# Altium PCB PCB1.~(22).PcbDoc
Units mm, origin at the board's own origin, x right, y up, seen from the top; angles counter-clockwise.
Board outline 24 x 24.06 mm, 2 copper layers (Top Layer, Bottom Layer); 41 components, 34 nets, 175 pads, 49 vias.
Unrouted connection lines stored in the file: 1.
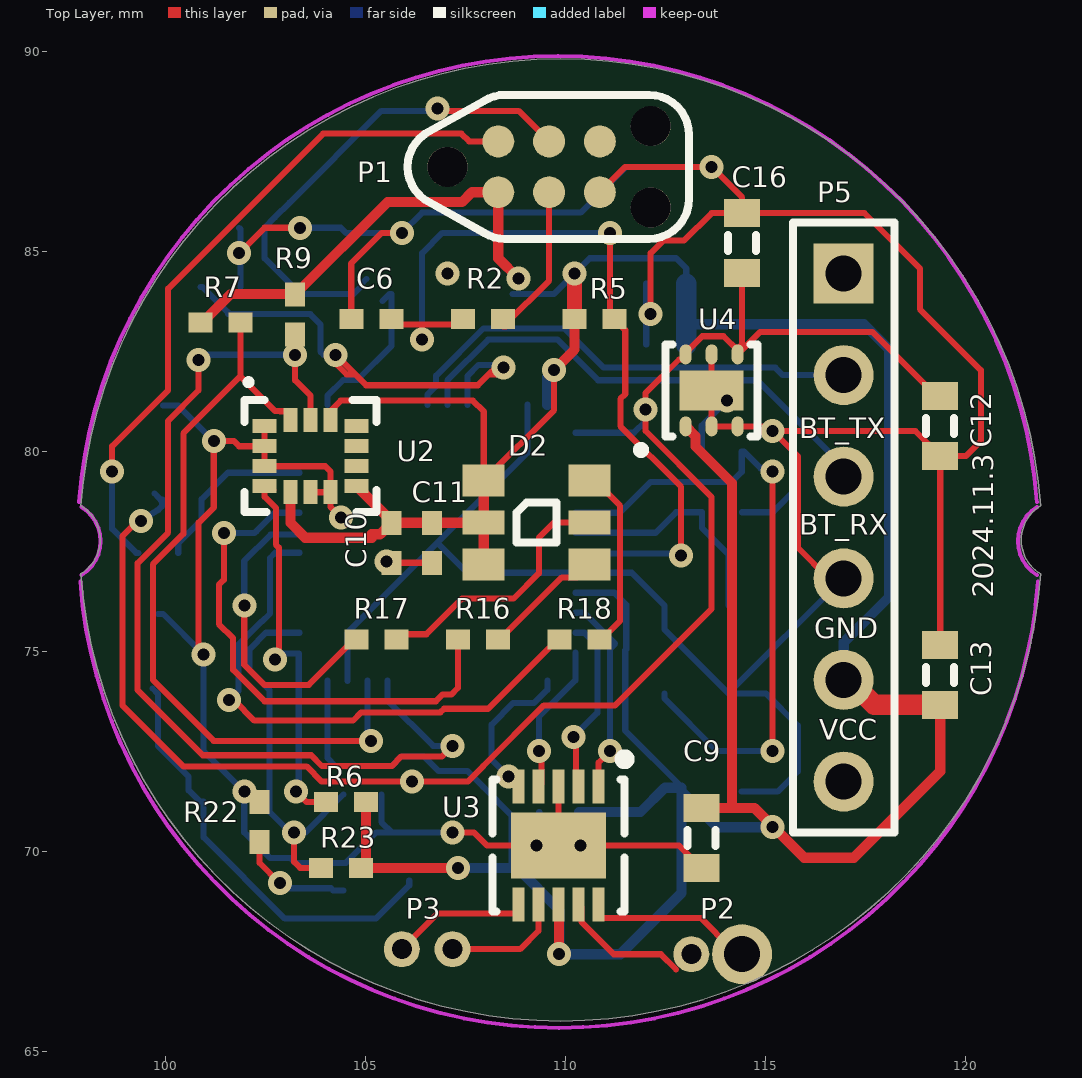
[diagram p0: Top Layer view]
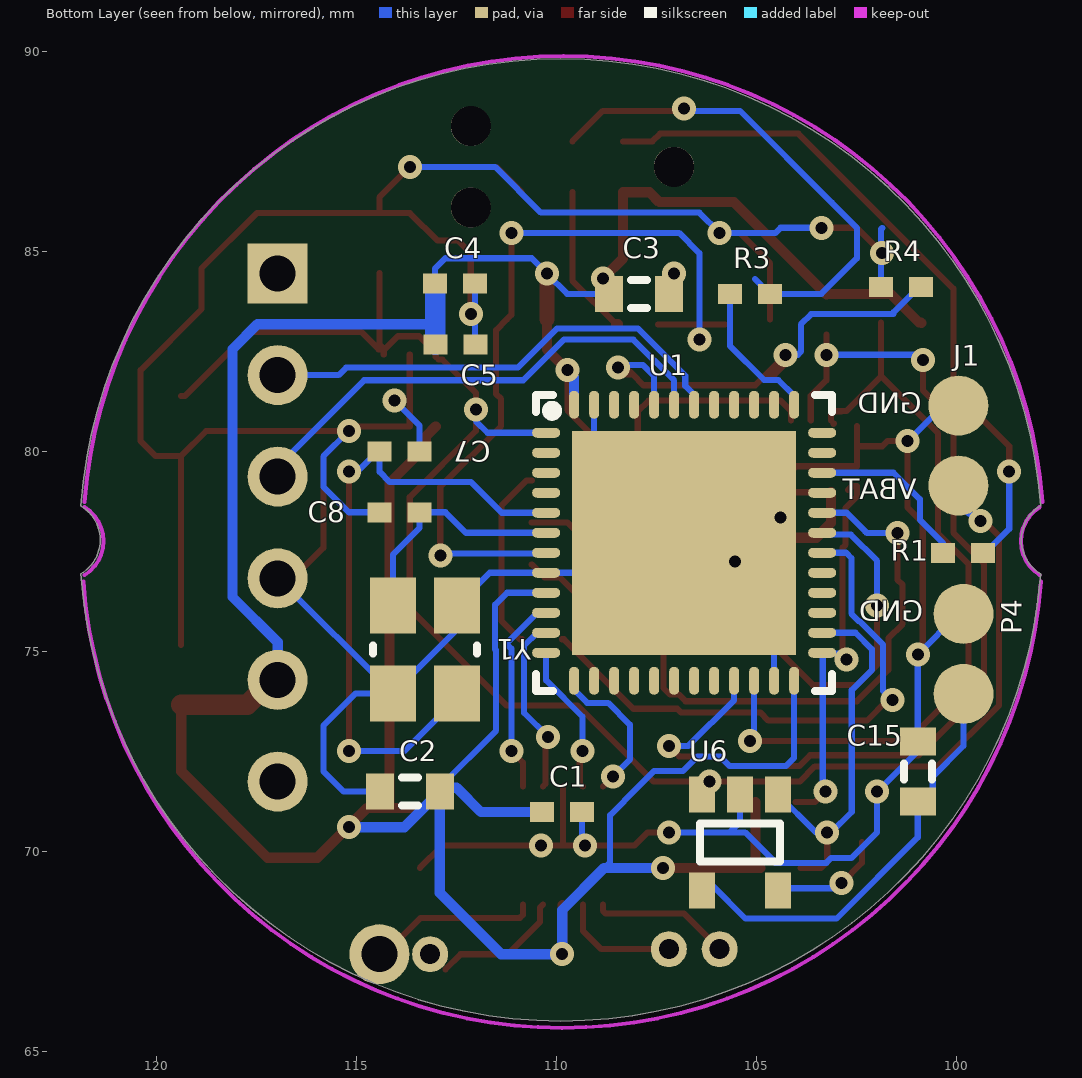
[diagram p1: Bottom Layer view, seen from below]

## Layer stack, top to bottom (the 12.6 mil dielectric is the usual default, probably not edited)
Top Solder: solder mask 0.0102, Solder Resist, Dk 3.5
Top Layer: signal copper 0.0356
Dielectric 1: dielectric 0.32, FR-4, Dk 4.8
Bottom Layer: signal copper 0.0356
Bottom Solder: solder mask 0.0102, Solder Resist, Dk 3.5

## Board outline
97.893,76.946 ccw(c97.392,77.796) 97.894,78.646 cw(c109.892,77.796) 121.89,78.648 121.891,78.646 ccw(c122.392,77.796) 121.89,76.946 cw(c109.892,77.796)

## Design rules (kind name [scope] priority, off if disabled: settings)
Clearance [All] p1: gap=0.254 except(0.127: Arc-Arc Track-SMDPad Arc-Track Arc-SMDPad Track-Track SMDPad-SMDPad)
PolygonConnect [All] p1: connectstyle=Relief reliefconductorwidth=0.254 reliefentries=4 polygonreliefangle="90 Angle" airgapwidth=0.254
RoutingVias [All] p1: holewidth=0.711 width=1.27 viastyle="Through Hole" minholewidth=0.711 minwidth=1.27 maxholewidth=0.711 maxwidth=1.27
SolderMaskExpansion [All] p1: expansion=0.102
UnpouredPolygon [All] p1: allowunpoured=FALSE
Width [All] p1: maxlimit=0.254 minlimit=0.127 preferedwidth=0.152 minimp=50.000000 maximp=50.000000 favimp=50.000000
29 further rules are at their usual default settings.

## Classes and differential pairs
net class MOTOR_CONTROL[1..4]: MOTOR_CONTROL1 MOTOR_CONTROL2 MOTOR_CONTROL3 MOTOR_CONTROL4
net class RGBLED[1..3]: RGBLED1 RGBLED2 RGBLED3

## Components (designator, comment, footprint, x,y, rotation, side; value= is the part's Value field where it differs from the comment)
C1 "10nF" 0402 109.855,70.993 r0 bottom
C2 "1uF" 0603 113.665,71.501 r180 bottom
C3 "4.7uF" 0603 107.938,83.947 r0 bottom
C4 "100nF" 0402 112.53,84.201 r0 bottom
C5 "100nF" 0402 112.522,82.677 r0 bottom
C6 "100nF" 0402 105.156,83.312 r0 top
C7 "22pF" 0402 113.919,80.01 r0 bottom
C8 "22pF" 0402 113.927,78.486 r180 bottom
C9 "10uF" 0603 113.411,70.346 r90 top
C10 "100nF" 0402 105.664,77.724 r90 top
C11 "100nF" 0402 106.68,77.724 r90 top
C12 "1uF" 0603 119.38,80.645 r90 top
C13 "1uF" 0603 119.38,74.422 r270 top
C15 "4.7uF" 0603 100.965,72.009 r270 bottom
C16 "4.7uF" 0603 114.427,85.217 r270 top
D2 "SMLVN6RGB1W1" "3.5x2.8 mm 6-SMD" 109.292,78.232 r0 top
J1 "78171-0002" "CHARGING PAD" 99.949,80.153 r90 bottom
P1 "TC2030-IDC-NL" TC2030-IDC-NL 109.601,87.122 r0 top
P2 "HEADER 2X1 0.05\" UNPOLARIZED" "HEADER 2X1 0.05\" - UNPOLARIZED"#1 113.792,67.437 r180 top
P3 "HEADER 2X1 0.05\" UNPOLARIZED" "HEADER 2X1 0.05\" - UNPOLARIZED"#2 106.553,67.564 r0 top
P4 "CHARGING PAD" "Charging Pad" 99.822,74.946 r90 bottom
P5 "Header 6" HDR1X6 116.967,84.455 r270 top
R1 "22R" 0402 99.83,77.47 r180 bottom
R2 "22R" 0402 107.95,83.312 r0 top
R3 "22R" 0402 105.164,83.947 r180 bottom
R4 "100K" 0402 101.384,84.121 r180 bottom
R5 "100K" 0402 110.736,83.312 r180 top
R6 "100K" 0402 104.521,71.247 r0 top
R7 "10K" 0402 101.384,83.232 r180 top
R9 "10K" 0402 103.251,83.431 r90 top
R16 "22.6R" 0402 107.823,75.311 r0 top
R17 "130R" 0402 105.283,75.311 r0 top
R18 "24.9R" 0402 110.363,75.311 r0 top
R22 "10K" 0402 102.362,70.739 r90 top
R23 "100K" 0402 104.394,69.596 r0 top
U1 "STM32F051C8U6" QFN50P700X700X60_HS-49L 106.807,77.724 r180 bottom
U2 "LSM6DS3" "LGA-14 2.5x3x0.86 mm 14L" 103.639,79.887 r0 top
U3 "A3901SEJTR-T" DFN50P300X300X75_HS-11N 109.839,70.153 r180 top
U4 "ADP122ACPZ-3.3-R7" "LFCSP-6 2.0X2.0X0.55" 113.665,81.534 r0 top
U6 "MCP73831T-2ACI/OT" SOT-23-OT5_L 105.41,70.231 r270 bottom
Y1 "7V-16.000MAAE-T" "3.2x2.5 CRYSTAL" 113.284,75.057 r90 bottom

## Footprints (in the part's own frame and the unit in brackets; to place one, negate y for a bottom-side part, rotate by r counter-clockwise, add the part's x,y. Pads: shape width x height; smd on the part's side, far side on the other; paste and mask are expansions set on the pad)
"3.2x2.5 CRYSTAL" [mm]
  rect 1.4x1.15 smd: 1(-1.1,-0.8) 2(1.1,-0.8) 3(1.1,0.8) 4(-1.1,0.8)
  silkscreen extent -0.1,-1.3 0.1,1.3, body extent -1.6,-1.25 1.6,1.25, height 0.8
"3.5x2.8 mm 6-SMD" [mm] "3.5 x 2.8 mm 6-SMD Flat Leads"
  rect 1.05x0.8 smd: 1(-1.325,1.05) 3(-1.325,-1.05) 4(1.325,-1.05) 6(1.325,1.05)
  rect 1.05x0.6 smd: 2(-1.325,0) 5(1.325,0)
  silkscreen extent -0.5,-0.5 0.5,0.5, body extent -1.75,-1.4 1.75,1.4, height 0.6
0402 [mm] "Chip Body 1.0 x 0.5 mm (LxW typ)"
  rect 0.6x0.5 smd: 1(-0.5,0) 2(0.5,0)
  body extent -0.55,-0.3 0.55,0.3, height 0.55
0603 [mm] "Chip Body 1.6 x 0.8 mm (LxW typ)"
  rect 0.7x0.9 smd: 1(-0.75,0) 2(0.75,0)
  silkscreen extent -0.2,-0.35 0.2,0.35, body extent -0.85,-0.48 0.85,0.48, height 0.9
"CHARGING PAD" [mm]
  round 1.5 smd paste-5: 1(-1,0) 2(1,0)
  body extent -1.75,-0.75 1.75,0.75, height 0
"Charging Pad" [mm]
  round 1.5 smd paste-5: 1(-1,0) 2(1,0)
  body extent -1.75,-0.75 1.75,0.75, height 0
DFN50P300X300X75_HS-11N [mm]
  rect 0.3x0.85 smd: 1(-1,-1.475) 2(-0.5,-1.475) 3(0,-1.475) 4(0.5,-1.475) 5(1,-1.475) 6(1,1.475) 7(0.5,1.475) 8(0,1.475) 9(-0.5,1.475) 10(-1,1.475)
  rect 2.38x1.65 smd: 11(0,0)
  silkscreen extent -1.78,-2.28 1.65,1.65, body extent -1.5,-1.5 1.5,1.5, height 0.75
HDR1X6 [mm] "Connector; Header; 6 Position"
  rect 1.5x1.5 hole 0.9: 1(0,0)
  round 1.5 hole 0.9: 2(2.54,0) 3(5.08,0) 4(7.62,0) 5(10.16,0) 6(12.7,0)
  silkscreen extent -1.27,-1.27 13.97,1.27
"HEADER 2X1 0.05\" - UNPOLARIZED"#1 [mm]
  round 1.5 hole 0.9: 1(-0.635,0)
  round 0.9 hole 0.5: 2(0.635,0)
  body extent -1.25,-0.6 1.25,0.6, height 0.01
"HEADER 2X1 0.05\" - UNPOLARIZED"#2 [mm]
  round 0.9 hole 0.5: 1(-0.635,0) 2(0.635,0)
  body extent -1.25,-0.6 1.25,0.6, height 0.01
"LFCSP-6 2.0X2.0X0.55" [mm] ". 6-Lead Lead Frame Chip Scale Package [LFCSP_UD]  2.00 mm?2.00 mm Body, Ultra Thin, Dual Lead  (CP-6-3)"
  oval 0.3x0.5 smd: 1(-0.65,-0.9) 2(0,-0.9) 3(0.65,-0.9) 4(0.65,0.9) 5(0,0.9) 6(-0.65,0.9)
  rect 1.6x1 smd: 7(0,0)
  silkscreen extent -1.86,-1.59 1.15,1.15, body extent -1,-1 1,1, height 0.6
"LGA-14 2.5x3x0.86 mm 14L" [mm] "LGA, 14-Leads, Body 3.00x2.50mm, Pitch 0.50mm, IPC High Density"
  rect 0.6x0.35 smd: 1(-1.15,0.75) 2(-1.15,0.25) 3(-1.15,-0.25) 4(-1.15,-0.75) 8(1.15,-0.75) 9(1.15,-0.25) 10(1.15,0.25) 11(1.15,0.75)
  rect 0.35x0.6 smd: 5(-0.5,-0.9) 6(0,-0.9) 7(0.5,-0.9) 12(0.5,0.9) 13(0,0.9) 14(-0.5,0.9)
  silkscreen extent -1.65,-1.4 1.65,1.9, body extent -1.5,-1.25 1.5,1.25, height 0.86
QFN50P700X700X60_HS-49L [mm] "QFN, 48-Leads, Body 7,00x7,00mm, Pitch 0,50mm, Thermal Pad 5,60x5,60mm, IPC High Density"
  oval 0.7x0.25 smd: 1(-3.45,2.75) 2(-3.45,2.25) 3(-3.45,1.75) 4(-3.45,1.25) 5(-3.45,0.75) 6(-3.45,0.25) 7(-3.45,-0.25) 8(-3.45,-0.75) 9(-3.45,-1.25) 10(-3.45,-1.75) 11(-3.45,-2.25) 12(-3.45,-2.75) 25(3.45,-2.75) 26(3.45,-2.25) 27(3.45,-1.75) 28(3.45,-1.25) 29(3.45,-0.75) 30(3.45,-0.25) 31(3.45,0.25) 32(3.45,0.75) 33(3.45,1.25) 34(3.45,1.75) 35(3.45,2.25) 36(3.45,2.75)
  oval 0.25x0.7 smd: 13(-2.75,-3.45) 14(-2.25,-3.45) 15(-1.75,-3.45) 16(-1.25,-3.45) 17(-0.75,-3.45) 18(-0.25,-3.45) 19(0.25,-3.45) 20(0.75,-3.45) 21(1.25,-3.45) 22(1.75,-3.45) 23(2.25,-3.45) 24(2.75,-3.45) 37(2.75,3.45) 38(2.25,3.45) 39(1.75,3.45) 40(1.25,3.45) 41(0.75,3.45) 42(0.25,3.45) 43(-0.25,3.45) 44(-0.75,3.45) 45(-1.25,3.45) 46(-1.75,3.45) 47(-2.25,3.45) 48(-2.75,3.45)
  rect 5.6x5.6 smd: 49(0,0)
  silkscreen extent -3.7,-3.7 3.7,3.7, body extent -3.55,-3.55 3.55,3.55, height 0.6
SOT-23-OT5_L [mm] "SOT23, 5-Leads, Body 2.9x1.6mm, Pitch 0.95mm, Lead Span 2.7mm, IPC High Density"
  rect 0.9x0.65 smd: 1(-1.2,0.95) 2(-1.2,0) 3(-1.2,-0.95) 4(1.2,-0.95) 5(1.2,0.95)
  silkscreen extent -0.48,-1 0.48,1, body extent -0.9,-1.55 0.9,1.55, height 1.45
TC2030-IDC-NL [mm] "TagConnector TC2030-IDC-NL"
  round 0.8 smd paste-1: 1(-1.27,-0.635) 2(-1.27,0.635) 3(0,-0.635) 4(0,0.635) 5(1.27,-0.635) 6(1.27,0.635)
  round 1 hole 1 unplated mask+0: ""(-2.54,0) ""(2.54,-1.016) ""(2.54,1.016)
  Top Layer pour cut-out: -1.27,-0.085 -1.27,0.085 -1.06,0.127 -0.881,0.246 -0.762,0.425 -0.72,0.635 -0.72,0.635 -0.55,0.635 -0.496,0.396 -0.343,0.205 -0.122,0.099 0.122,0.099 0.343,0.205 0.496,0.396 0.55,0.635 0.55,0.635 0.72,0.635 0.762,0.425 0.881,0.246 1.06,0.127 1.27,0.085 1.27,0.085 1.27,-0.085 1.06,-0.127 0.881,-0.246 0.762,-0.425 0.72,-0.635 0.72,-0.635 0.55,-0.635 0.496,-0.396 0.343,-0.205 0.122,-0.099 -0.122,-0.099 -0.343,-0.205 -0.496,-0.396 -0.55,-0.635 -0.55,-0.635 -0.72,-0.635 -0.762,-0.425 -0.881,-0.246 -1.06,-0.127 -1.27,-0.085
  silkscreen extent -3.54,-1.8 3.5,1.8, body extent -1.67,-1.03 1.67,1.03, height 0

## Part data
C1: "10nF 0402 X7R 25V ±5%"
C2 C12 C13: "1uF 0603 X5R 10V ±10%"
C3 C15 C16: "4.7uF 0603 X5R 10V ±10%"
C4 C5 C6 C10 C11: "100nF 0402 X7R 16V ±10%"
C7 C8: "22pF 0402 NP0/CG0 50V ±5%"
C9: "10uF 0603 X5R 6.3V ±20%"
D2: "ROHM SMLVN6RGB1W1 LED Tri-Color Blue/Green/Red Chip LED 6-Pin 1411 T/RLED Tri-Color Blue/Green/Red Chip LED 6-Pin 1411"
J1: "Molex Pico-EZmate? Wire-to-Board Header, 2 contacts"
P1: "TagConnect TC2030-IDC-NL SWD Programming Connector"
P5: "Header, 6-Pin"
R1 R2 R3: "22R 0402 1/16W ±1%"
R4 R5 R6 R23: "100K 0402 1/16W ±1%"
R7 R9 R22: "10K 0402 1/16W ±1%"
R16: "22.6R 0402 1/16W ±0.05R"
R17: "130R 0402 1/16W ±0.05R"
R18: "24.9R 0402 1/16W ±0.05R"
U1: "STMICROELECTRONICS  STM32F051C8U6  MCU 32BIT CORTEX-M0 48MHZ UFQFPN-48"
U2: "STMicroelectronics iNEMO inertial module:   3D accelerometer and 3D gyroscope"
U3: "ALLEGRO MICROSYSTEMS - A3901SEJTR-T - IC, MOTOR DRIVER"
U4: "Analog Devices ADP122ACPZ-3.3-R7 - 5.5 V Input, 300 mA, Low Quiescent  Current, CMOS Linear Regulator"
U6: "Miniature Single-Cell, Fully Integrated Li-Ion, Li-Polymer Charge Management Controller, 4.2V, 5-Pin SOT-23, Industrial Temperature, Tape and Reel"
Y1: "TXC - 7V-16.000MAAE-T, 16MHZ, 30PPM, 12PF - CRYSTAL"

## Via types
v1: diameter 0.6, hole 0.3, Top Layer to Bottom Layer, 49 vias

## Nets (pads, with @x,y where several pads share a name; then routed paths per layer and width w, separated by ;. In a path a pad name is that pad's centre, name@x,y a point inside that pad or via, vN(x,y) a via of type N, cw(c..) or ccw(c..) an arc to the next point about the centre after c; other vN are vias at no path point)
+3.3V: C1.2 C2.2 C3.2 C4.2 C5.2 C9.2 C10.2 C11.2 C13.2 D2.1 D2.2 D2.3 P1.1 P5.5 R5.2 R6.2 R7.2 R9.2 R23.2 U1.9 U1.24 U1.48 U2.5 U2.8 U2.12 U3.8 U4.1 | length 112.6
  Top Layer w0.152: U2.12 104.139,81.025 104.394,81.28 107.696,81.28 107.967,81.009 D2.1 109.727,81.042 v1(109.727,82.043) ; U3.8 U3.8@109.847,68.67 ; v1@109.847,67.445 v1(109.855,67.437) ; P5.5 P5.5@117.105,74.295
  Top Layer w0.254: R7.2@100.868,83.216 R7.2 100.934,83.232 101.649,83.947 103.235,83.947 R9.2 105.561,86.241 107.426,86.241 107.672,86.487 P1.1 108.331,84.836 v1(108.838,84.329) ; U2.5 103.139,78.217 103.505,77.851 105.169,77.851 105.169,77.937 105.377,77.937 C10.2 C11.2 D2.2@107.959,78.224 ; U2.8 C10.2@105.664,78.262 ; R6.2 105.021,69.723 R23.2 v1(107.33,69.597) v1@107.458,69.469 ; D2.3 D2.2 D2.1 ; v1(109.727,82.043) 110.236,82.552 R5.2 ; v1@109.847,67.445 U3.8@109.847,68.67 ; U4.1 113.261,80.388 113.261,80.13 114.173,79.218 114.173,71.096 ; C9.2 114.173,71.096 ; C13.2 119.38,72.009 117.221,69.85 115.977,69.85 114.731,71.096 114.173,71.096
  Top Layer w0.381: R5.2 v1(110.236,84.455)
  Top Layer w0.508: P5.5@117.105,74.295 117.728,73.672 C13.2
  Bottom Layer w0.152: U1.24 104.057,72.346 104.261,72.142 105.668,72.142 105.911,72.385 106.468,72.385 106.84,72.014 107.564,72.014 107.955,71.623 107.955,71.621 108.659,70.917 108.659,69.74 108.802,69.597 ; C3.2 109.728,83.947 v1(110.236,84.455) 110.617,84.836 112.776,84.836 113.03,84.582 C4.2 ; U1.9 111.232,76.474 111.531,76.175 111.531,75.063 111.506,75.037 111.506,73.027 112.915,71.618 112.915,71.601 C2.2
  Bottom Layer w0.254: v1(107.33,69.597) 108.802,69.597 109.855,68.544 v1(109.855,67.437) 111.379,67.437 112.915,68.973 C2.2 113.803,70.613 v1(115.188,70.613) ; U1.48 109.557,81.871 v1@109.601,81.915 ; C1.2 111.887,70.993 112.495,71.601 C2.2@112.915,71.601 ; 113.03,83.185 117.475,83.185 118.098,82.562 118.098,76.367 116.967,75.236 P5.5
  Bottom Layer w0.508: C5.2@113.03,82.677 113.03,83.185 C4.2
BT_RX: P5.3 U1.43 | length 12.5
  Bottom Layer w0.152: U1.43 107.057,81.784 108.077,82.804 109.813,82.804 110.829,81.788 114.808,81.788 116.967,79.629 P5.3
BT_TX: P5.2 U1.42 | length 12
  Bottom Layer w0.152: U1.42 106.557,81.425 106.778,81.646 106.778,81.9 107.961,83.083 109.982,83.083 110.964,82.102 115.256,82.102 115.443,81.915 P5.2
CHARGING: R23.1 U1.26 U6.1 | length 9.6
  Top Layer w0.152: v1(103.229,70.486) 103.229,69.747 103.38,69.596 R23.1
  Bottom Layer w0.152: U1.26 102.523,75.474 102.113,75.064 102.113,74.542 102.482,74.173 102.484,74.173 102.616,74.041 102.616,70.993 103.124,70.485 103.514,70.485 U6.1
GND: C1.1 C2.1 C3.1 C4.1 C5.1 C6.1 C7.1 C8.1 C9.1 C10.1 C11.1 C12.1 C13.1 C15.1 C16.1 J1.2 P1.5 P4.2 P5.4 R4.1 R22.2 U1.8 U1.23 U1.47 U1.49 U2.1 U2.2 U2.3 U2.6 U2.7 U3.3 U3.11 U4.2 U4.3 U4.5 U4.7 U6.2 Y1.2 Y1.4 | length 123.8
  Top Layer w0.152: v1(100.965,74.93) 100.841,75.054 100.841,78.226 101.219,78.604 v1(101.219,80.264) 101.727,80.264 101.854,80.137 U2.2 ; v1(101.854,84.963) 102.49,85.599 v1(103.378,85.599) ; U2.1 U2.2 ; U2.6 U2.7 ; v1(104.394,78.359) 104.139,78.614 U2.7 ; C6.1 104.656,84.709 105.418,85.471 v1(105.918,85.471) ; C10.1 C11.1 ; v1(107.188,70.485) 107.721,70.485 108.053,70.153 v1(109.289,70.153) U3.11 ; U3.3 U3.11 ; P1.5 111.506,87.122 v1(113.665,87.122) 114.427,86.36 C16.1 ; v1(112.141,83.439) 112.141,84.963 112.454,85.276 112.971,85.276 113.662,85.967 C16.1 ; C9.1 112.854,70.153 v1(110.389,70.153) U3.11 ; U4.5 U4.7 U4.2 U4.3 115.073,80.634 v1(115.189,80.518) ; P5.4 116.586,76.835 115.824,77.597 115.824,79.883 v1(115.189,80.518) ; C13.1 C12.1 ; U2.2 U2.3 104.005,79.637 104.139,79.503 U2.7 ; C16.1 117.487,85.967 118.872,84.582 118.872,83.566 120.396,82.042 120.396,80.264 120.027,79.895 C12.1 ; v1(115.189,80.518) 118.757,80.518 C12.1
  Bottom Layer w0.152: P4.2 99.949,75.946 v1(100.965,74.93) C15.1 100.965,72.517 v1(101.981,71.501) 101.981,70.485 102.62,69.846 103.13,69.846 103.253,69.723 104.521,69.723 105.283,70.485 105.664,70.485 ; J1.2 100.33,81.153 v1(101.219,80.264) ; 101.854,85.598 101.884,85.568 R4.1 ; v1(103.378,85.599) 104.393,85.599 104.521,85.471 v1(105.918,85.471) 106.426,85.979 110.389,85.979 111.532,87.122 v1(113.665,87.122) ; U1.23 104.557,75.474 U1.49 ; U6.2 105.41,70.739 105.664,70.485 ; v1(107.188,70.485) 105.664,70.485 ; U1.47 109.057,79.974 U1.49 ; v1(109.289,70.153) 109.355,70.219 C1.1 ; C5.1@112.03,82.677 C4.1 ; C7.1 113.419,80.653 v1(114.046,81.28) ; C2.1 115.316,71.501 115.824,72.009 115.824,73.152 115.019,73.957 Y1.4 ; C8.1 115.189,78.486 115.824,79.121 115.824,79.883 v1(115.189,80.518) ; P5.4 116.962,76.835 Y1.4 ; U1.49 107.557,76.974 U1.8 111.667,76.974 Y1.2 112.484,75.557 Y1.4
  other v1: 105.537,77.256 107.061,84.455
I2C.SCL: R9.1 U1.21 U2.13 | length 25.1
  Top Layer w0.152: v1(100.837,82.297) 100.837,81.533 100.076,80.772 100.076,77.978 99.314,77.216 99.314,74.041 100.944,72.411 103.655,72.411 103.924,72.142 105.668,72.142 105.911,72.385 106.929,72.385 v1(107.188,72.644) ; R9.1 103.251,81.788 103.64,81.399 U2.13 U2.13
  Bottom Layer w0.152: v1@100.839,82.424 v1(103.25,82.424) ; U1.21 105.557,73.787 106.7,72.644 v1(107.188,72.644)
I2C.SDA: R7.1 U1.22 U2.14 | length 19.3
  Top Layer w0.152: R7.1 101.884,81.885 ; U2.14@103.06,80.709 U2.14@103.076,80.693 ; U2.14 103.139,80.912 103.04,81.011 102.878,81.011 102.873,81.015 102.754,81.015 101.884,81.885 ; v1(105.155,72.772) 101.219,72.771 99.695,74.295 99.695,77.182 100.457,77.944 100.457,80.458 101.884,81.885
  Bottom Layer w0.152: U1.22 105.057,72.87 v1(105.155,72.772)
IMU_INT: R6.1 U1.25 U2.4 | length 9.7
  Top Layer w0.152: U2.4@102.713,79.038 102.614,79.137 U2.4 102.489,78.875 102.769,78.594 102.769,77.676 102.846,77.599 102.846,75.031 v1@102.755,74.94 ; v1(103.278,71.502) 103.533,71.247 R6.1
  Bottom Layer w0.152: v1(102.743,74.803) 102.743,74.928 102.771,74.955 103.338,74.955 103.342,74.959 103.342,71.566 v1(103.278,71.502)
MCU_X1_16MHZ: C7.2 U1.5 Y1.1 | length 16.4
  Top Layer w0.152: v1(115.189,72.517) v1(115.189,79.502)
  Bottom Layer w0.152: U1.5 111.367,78.474 112.141,79.248 114.173,79.248 114.419,79.494 C7.2 114.469,80.01 114.891,79.588 115.103,79.588 v1(115.189,79.502) ; Y1.1 112.484,73.832 113.799,72.517 v1(115.189,72.517)
MCU_X2_16MHZ: C8.2 U1.6 Y1.3 | length 6
  Bottom Layer w0.152: U1.6 112.264,77.974 112.776,78.486 C8.2 113.427,78.089 114.084,77.432 Y1.3
MOTOR_CONTROL1: U1.10 U3.1 | length 5.1
  Top Layer w0.152: U3.1 110.839,72.231 v1(111.125,72.517)
  Bottom Layer w0.152: U1.10 110.482,75.974 111.252,75.204 111.125,75.077 v1(111.125,72.517)
MOTOR_CONTROL2: U1.11 U3.2 | length 4.5
  Top Layer w0.152: v1(110.209,72.872) 110.274,72.807 110.274,71.693 U3.2
  Bottom Layer w0.152: v1(110.209,72.872) 110.81,73.474 110.81,75.146 110.482,75.474 U1.11
MOTOR_CONTROL3: U1.12 U3.4 | length 3.9
  Top Layer w0.152: U3.4 109.413,71.702 109.413,72.063 109.416,72.066 109.416,72.581 109.347,72.512 v1(109.347,72.517)
  Bottom Layer w0.152: v1(109.347,72.517) 109.347,73.375 110.257,74.285 U1.12
MOTOR_CONTROL4: U1.13 U3.5 | length 3.8
  Top Layer w0.152: v1(108.585,71.882) U3.5
  Bottom Layer w0.152: v1(108.585,71.882) 108.163,72.304 108.163,73.178 108.705,73.721 109.229,73.721 109.557,74.049 U1.13
NetC15_2: C15.2 P4.1 U6.4 | length 10.8
  Bottom Layer w0.152: P4.1@99.687,74.081 P4.1 99.822,72.644 100.591,71.875 100.591,71.533 100.865,71.259 C15.2 100.965,70.358 102.997,68.326 105.272,68.326 106.106,69.16 U6.4@106.106,69.285
NetD2_4: D2.4 R16.2 | length 3.1
  Top Layer w0.152: R16.2 108.373,75.311 109.92,76.858 110.293,76.858 D2.4
NetD2_5: D2.5 R17.2 | length 6.5
  Top Layer w0.152: R17.2@105.783,75.438 106.535,75.438 107.424,76.327 108.712,76.327 109.347,76.962 109.347,77.851 109.728,78.232 D2.5
NetD2_6: D2.6 R18.2 | length 4.6
  Top Layer w0.152: D2.6 110.742,79.282 111.377,78.647 111.377,75.775 110.913,75.311 R18.2
NetP1_2: P1.2 R1.2 | length 17.4
  Top Layer w0.152: v1(98.679,79.502) 98.679,80.137 100.076,81.534 100.076,84.074 103.954,87.952 107.405,87.952 107.6,87.757 P1.2
  Bottom Layer w0.152: v1(98.679,79.502) 98.679,78.071 99.28,77.47 R1.2
NetP1_3: P1.3 R2.2 | length 3.8
  Top Layer w0.152: R2.2@108.508,83.185 109.601,84.278 P1.3
  Top Layer w0.254: R2.2@108.458,83.185 R2.2@108.508,83.185
NetP1_4: P1.4 R3.2 | length 12.6
  Top Layer w0.152: v1(106.807,88.582) 106.87,88.519 108.839,88.519 P1.4
  Bottom Layer w0.152: 105.037,84.32 104.888,84.171 104.888,84.121 104.714,83.947 R3.2 103.378,83.947 102.489,84.836 102.489,85.598 102.748,85.857 102.748,85.86 103.117,86.229 103.12,86.229 105.41,88.519 106.744,88.519 v1(106.807,88.582)
NetP2_1: P2.1 U3.10 | length 3.9
  Top Layer w0.152: U3.10 110.839,68.418 110.913,68.344 113.393,68.344 P2.1@114.173,67.564
NetP2_2: P2.2 U3.9 | length 3.3
  Top Layer w0.152: U3.9 110.413,68.604 110.413,68.242 111.218,67.437 112.395,67.437 112.776,67.056
NetP3_1: P3.1 U3.6 | length 3.5
  Top Layer w0.152: P3.1 106.807,68.453 108.765,68.453 108.839,68.527 U3.6
NetP3_2: P3.2 U3.7 | length 3
  Top Layer w0.152: P3.2 108.877,67.564 109.337,68.024 109.337,68.676 U3.7
NetR4_2: R4.2 U1.44 | length 12.3
  Top Layer w0.152: v1@104.161,82.423 104.104,82.366 104.537,81.932 104.758,81.932 ; v1(104.267,82.423) 104.758,81.932 ; 104.758,81.932 105.029,81.661 107.823,81.661 108.094,81.932 ; 108.094,81.932 108.289,81.932 v1(108.458,82.102) 108.264,82.102 108.094,81.932
  Bottom Layer w0.152: R4.2 100.934,84.121 101.569,83.486 ; 101.569,83.439 103.632,83.439 103.886,83.185 103.886,82.503 103.966,82.423 v1(104.267,82.423) ; U1.44 107.557,81.889 107.837,82.169 108.391,82.169 v1(108.458,82.102)
NetR22_1: R22.1 U6.5 | length 3.1
  Top Layer w0.152: R22.1 102.362,69.723 v1(102.869,69.216) v1@102.997,69.088
  Bottom Layer w0.152: v1(102.869,69.216) 102.997,69.088 104.149,69.088 104.206,69.031 U6.5
NRST: C6.2 R2.1 R5.1 U1.7 | length 20.6
  Top Layer w0.152: C6.2@105.791,83.185 106.426,83.185 ; v1(106.426,82.804) 106.426,83.185 ; R2.1@107.458,83.185 106.426,83.185 ; v1(111.124,85.472) 111.124,83.424 R5.1 111.506,83.042 111.506,81.441 111.384,81.319 111.384,80.64 112.903,79.121 v1(112.903,77.411)
  Bottom Layer w0.152: v1(106.426,82.804) 106.426,84.961 106.425,84.962 106.934,85.471 v1@110.998,85.471 ; U1.7 110.508,77.474 110.527,77.455 112.859,77.455 v1(112.903,77.411)
RGBLED1: R17.1 U1.31 | length 7.7
  Top Layer w0.152: v1(101.981,76.157) 101.981,74.674 102.482,74.173 103.595,74.173 104.733,75.311 R17.1
  Bottom Layer w0.152: v1(101.981,76.157) 101.981,77.269 102.641,77.929 U1.31@103.312,77.929
RGBLED2: R16.1 U1.32 | length 13
  Top Layer w0.152: v1(101.471,77.965) 101.473,77.963 101.473,76.8 101.346,76.673 101.346,75.692 101.702,75.336 101.702,74.549 102.489,73.762 106.77,73.762 106.934,73.926 107.155,73.926 107.323,74.094 R16.1
  Bottom Layer w0.152: v1(101.471,77.965) 102.237,77.965 102.281,78.01 102.746,78.474 U1.32
RGBLED3: R18.1 U1.30 | length 14.1
  Top Layer w0.152: v1(101.6,73.787) 101.727,73.787 102.235,73.279 104.699,73.279 104.902,73.482 106.885,73.482 106.978,73.575 108.077,73.575 109.813,75.311 R18.1
  Bottom Layer w0.152: v1(101.6,73.787) 101.833,74.02 101.833,75.18 102.407,75.753 102.423,75.753 102.624,75.954 102.624,77.343 102.755,77.474 U1.30
SWCLK: R3.1 U1.37 | length 3.9
  Bottom Layer w0.152: U1.37 104.057,81.399 104.451,81.793 104.808,81.793 105.664,82.649 R3.1 105.614,83.947 R3.1@105.44,83.773
SWDIO: R1.1 U1.34 | length 4.3
  Bottom Layer w0.152: R1.1 100.33,77.715 100.913,78.298 100.913,78.815 101.572,79.474 U1.34
VBAT: C12.2 C16.2 J1.1 U1.1 U4.4 U4.6 U6.3 | length 42.5
  Top Layer w0.152: v1(99.399,78.274) 99.318,78.274 98.933,77.889 98.933,73.66 100.461,72.132 103.539,72.132 103.916,71.755 v1(106.172,71.755) 107.569,71.755 107.955,72.141 107.955,72.143 109.472,73.66 111.252,73.66 113.665,76.073 113.665,78.867 112.014,80.518 v1(112.014,81.058) 112.014,81.47 112.849,82.306 112.947,82.306 113.015,82.374 U4.6 113.015,82.471 113.431,82.887 113.962,82.887 114.315,82.534 U4.4 ; U4.4@114.315,82.574 114.427,82.686 C16.2 ; U4.4@114.383,82.562 114.443,82.562 114.876,82.995 117.68,82.995 119.28,81.395 C12.2
  Bottom Layer w0.152: v1(99.399,78.274) 99.833,78.548 99.922,78.637 99.939,78.808 99.937,78.745 J1.1@99.739,78.955 ; U1.1 111.722,80.474 112.014,80.766 v1(112.014,81.058)
pads on no net: P1. P1.6 P5.1 P5.6 U1.2 U1.3 U1.4 U1.14 U1.15 U1.16 U1.17 U1.18 U1.19 U1.20 U1.27 U1.28 U1.29 U1.33 U1.35 U1.36 U1.38 U1.39 U1.40 U1.41 U1.45 U1.46 U2.9 U2.10 U2.11

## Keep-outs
Keep-Out Layer:
  lines w0.1: 97.853,78.74 cw(c109.823,77.892) 121.793,78.74 ; 97.885,76.749 ccw(c109.855,77.597) 121.825,76.749 ; 97.917,76.917 ccw(c97.387,77.765) 97.917,78.613 ; 121.793,76.917 cw(c122.323,77.765) 121.793,78.613

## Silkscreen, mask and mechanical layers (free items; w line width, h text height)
Top Overlay:
  text "BT_TX" at 115.849,80.332 h0.51
  text "BT_RX" at 115.849,77.919 h0.51
  text "2024.11.3" at 120.709,76.352 h0.51 r90
  text "GND" at 116.23,75.336 h0.51
  text "VCC" at 116.357,72.796 h0.51
Bottom Overlay:
  text "GND" at 100.863,80.967 h0.51
  text "VBAT" at 100.99,78.808 h0.51
  text "GND" at 100.823,75.76 h0.51
Mechanical 2:
  lines w0.254: 97.893,76.946 ccw(c97.392,77.796) 97.894,78.646 cw(c109.892,77.796) 121.89,78.648 ; 97.894,76.944 ccw(c109.892,77.796) 121.89,76.946 cw(c122.392,77.796) 121.891,78.646
Mechanical 10:
  lines w0.1: 97.885,78.699 cw(c109.855,77.851) 121.825,78.699 ; 97.855,76.943 ccw(c109.825,77.791) 121.795,76.943 ; 97.855,76.943 ccw(c97.325,77.791) 97.855,78.639 ; 97.855,76.943 ccw(c97.325,77.791) 97.855,78.639 ; 97.855,76.943 ccw(c109.825,77.791) 121.795,76.943 ; 97.855,78.639 cw(c109.825,77.791) 121.795,78.639 ; 97.855,78.639 cw(c109.825,77.791) 121.795,78.639 ; 97.982,76.943 ccw(c97.452,77.791) 97.982,78.639 ; 97.982,76.943 ccw(c109.952,77.791) 121.922,76.943 ; 97.982,76.943 ccw(c109.952,77.791) 121.922,76.943 ; 97.982,76.943 ccw(c97.452,77.791) 97.982,78.639 ; 97.982,78.639 cw(c109.952,77.791) 121.922,78.639 ; 97.982,78.639 cw(c109.952,77.791) 121.922,78.639 ; 121.795,76.943 cw(c122.325,77.791) 121.795,78.639 ; 121.795,76.943 cw(c122.325,77.791) 121.795,78.639 ; 121.922,76.943 cw(c122.452,77.791) 121.922,78.639 ; 121.922,76.943 cw(c122.452,77.791) 121.922,78.639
